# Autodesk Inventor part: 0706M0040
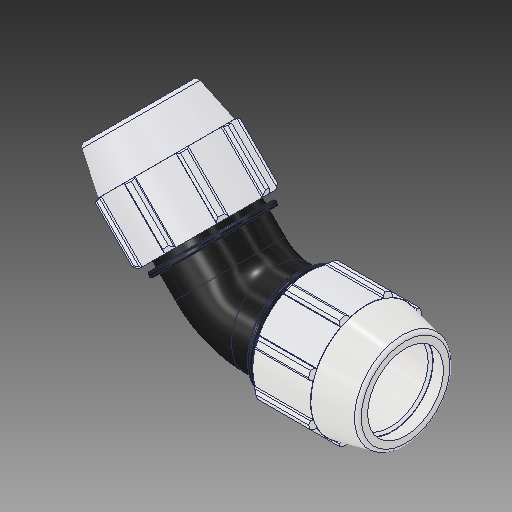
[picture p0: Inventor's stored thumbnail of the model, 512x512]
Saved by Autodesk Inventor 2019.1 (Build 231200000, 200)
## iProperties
Created: 2017-02
Part Number: 0706M0040
Material: PVC-Piping
Description: PLASSON 45° ELBOW 4'' - 4''
Document SubType Name: Modeling
Designer: KIM
Mass: 92.6774 g
Surface Area: 199.44 cm^2
Volume: 66.1981 cm^3
Density: 1.4 g/cm^3
Appearance: PTFE
Author: KIM
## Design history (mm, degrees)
derived "0706M0.ipt"
feature "Solid1::0706M0.ipt"
tag "TaggingFeature1"
body "Solid1"
other parameters: "d2" = 114.1, "d4" = 19.57917, "d5" = 58.7375, "d7" = 181.102, "d9" = 33.56429, "d11" = 7.83167, "d13" = 120 deg, "d14" = 142.625, "d15" = 12 deg, "d16" = 157.55874, "d18" = 5.705, "d19" = 35 deg, "d20" = 17.5 deg, "d21" = 168.42486, "d23" = 0, "d25" = 360 deg, "d27" = 3.62204, "d33" = 2.282, "d42" = 86.9315, "d43" = 5.43306, "d46" = 3.423, "d51" = 234.95, "d59" = 135 deg, "d63" = 194.056, "d67" = 135.8265, "d68" = 7.83167, "d72" = 1.5, "d73" = 0, "d74" = 0, "d_" = 114.1, "E_" = 181.102, "A_" = 234.95, "l_" = 194.056
